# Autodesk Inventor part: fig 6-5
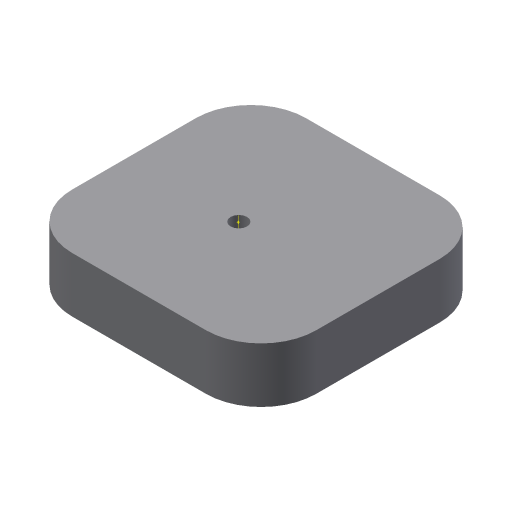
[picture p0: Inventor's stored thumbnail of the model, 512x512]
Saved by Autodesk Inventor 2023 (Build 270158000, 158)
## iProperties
Created: 2004-05
Part Number: fig 6-5
Document SubType Name: Modeling
Designer: CADCIM Technologies
Manufacturer: Standard
Standards Organization: Custom
Density: 1 g/cm^3
Material: Generic
Appearance: Default
Author: CADCIM Technologies
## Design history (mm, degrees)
sketch "Sketch1"
  geometry: L1 (0, 0)-(44.293, 0); L2 (44.293, 0)-(44.293, 42.442); L3 (44.293, 42.442)-(0, 42.442); L4 (0, 42.442)-(0, 0)
  constraints: 8 end point, 2 parallel, 1 horizontal, 1 perpendicular
extrude "Extrusion1" new body sketch "Sketch1" distance "d0" = 10; taper "d1" = 0 deg
fillet "Fillet1" dims "d2" = 10
sketch "Sketch2"
  geometry: 1 further point
sketch "Sketch3"
  geometry: L1 (10, 42.442)-(34.293, 42.442) reference; L2 (0, 10)-(0, 32.442) reference; L3 (34.293, 0)-(10, 0) reference; L4 (44.293, 32.442)-(44.293, 10) reference; A1 r 10 centre (34.293, 32.442) between (44.293, 32.442) and (34.293, 42.442) reference; A2 r 10 centre (10, 32.442) between (10, 42.442) and (0, 32.442) reference; A3 r 10 centre (10, 10) between (0, 10) and (10, 0) reference; A4 r 10 centre (34.293, 10) between (34.293, 0) and (44.293, 10) reference; 1 further point
workaxis "Work Axis1"
  workpoint "Work Point1"
hole "Hole3" diameter "d24" = 3; stored, may be unused: countersink angle "d28" = 90 deg, drill point angle "d30" = 118 deg; dims "d22" = 10, "d23" = 10, "d25" = 6, "d26" = 4, "d27" = 2, "d29" = 8
body "Solid1"
